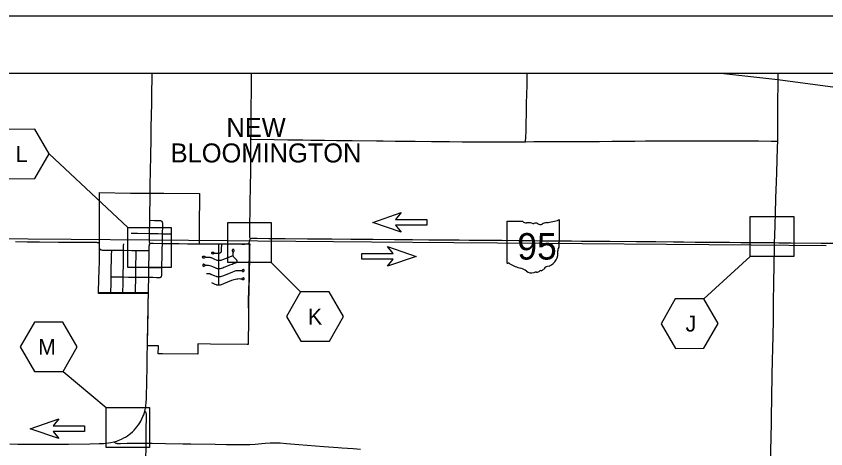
# Model space of a CAD drawing. Extents: x 0 to 680, y 0 to 440.
# Drawn here: x 190.2 to 332.1, y 364.2 to 440 of the extents above; entities that cross this region are included whole.
import ezdxf

# ---------------------------------------------------------------- set-up
doc = ezdxf.new("R2010")
doc.units = 0
for name, color, linetype in [('DV_X_Corp_Line', 7, 'Continuous'), ('GM_X_City_Street', 7, 'Continuous'), ('GM_X_Corporation_Text', 7, 'Continuous'), ('GM_X_County_Road', 7, 'Continuous'), ('GM_X_State_Location', 7, 'Continuous'), ('GM_X_State_Route', 7, 'Continuous'), ('GM_X_State_Shield', 7, 'Continuous'), ('GM_X_Township_Road', 7, 'Continuous'), ('PM_P_Cells', 7, 'Continuous'), ('RD_X_RR_2', 7, 'Continuous'), ('SC_Shading3', 7, 'Continuous'), ('SH_Border', 7, 'Continuous'), ('SH_Cut_Line', 7, 'Continuous'), ('SH_Text', 7, 'Continuous')]:
    doc.layers.add(name, color=color, linetype=linetype)

msp = doc.modelspace()

# ---------------------------------------------------------------- linework, layer by layer
at = {"layer": 'DV_X_Corp_Line'}
msp.add_lwpolyline([(231.1, 399.91), (231.09, 399.7), (231.09, 399.37), (231.08, 398.58), (231.07, 398.08), (231.07, 397.98), (231.01, 394.64), (230.96, 392.12), (230.92, 389.86), (230.87, 387.26), (230.87, 386.43), (230.84, 383.1), (230.84, 382.49), (230.64, 382.49), (224.26, 382.54), (222.03, 382.57), (222.02, 380.76), (215.82, 380.81), (215.09, 380.82), (215.11, 382.12), (215.11, 382.22), (214.91, 382.22), (213.52, 382.23), (213.39, 382.23), (213.19, 382.23), (213.2, 382.65), (213.22, 383.91), (213.24, 384.93), (213.24, 385.28), (213.26, 386.01), (213.31, 389.08), (213.31, 389.18), (213.31, 389.21), (213.33, 390.09), (213.35, 390.87), (213.36, 391.38), (213.16, 391.38), (211.27, 391.39), (210.02, 391.4), (205.38, 391.42), (204.59, 391.43), (204.59, 391.48), (204.59, 391.63), (204.59, 391.68), (204.6, 391.83), (204.61, 392.21), (204.62, 392.6), (204.64, 392.98), (204.65, 393.37), (204.67, 393.75), (204.68, 394.03), (204.68, 394.14), (204.69, 394.52), (204.71, 394.91), (204.72, 395.29), (204.73, 395.68), (204.75, 396.06), (204.76, 396.45), (204.77, 398.01), (204.77, 398.8), (204.78, 400.39), (204.78, 400.51), (204.78, 400.59), (204.78, 400.84), (204.78, 401.17), (204.78, 403.01), (204.76, 409.08), (210.21, 409), (211.53, 408.99), (213.48, 408.98), (213.68, 408.98), (213.88, 408.98), (214.76, 408.98), (214.87, 408.97), (216.04, 408.97), (222.33, 408.93), (222.26, 402.94), (222.24, 401.1), (222.24, 400.98), (222.25, 400.32), (222.25, 400.18), (222.25, 400.12), (223.84, 400.11), (225.4, 400.12), (225.64, 400.12), (227.83, 400.13), (228.56, 400.1), (229.18, 400.09), (229.77, 400.09), (231.1, 400.09)], close=True, dxfattribs=at)
at = {"layer": 'GM_X_City_Street'}
msp.add_line((225.68, 394.35), (225.69, 395.76), dxfattribs=at)
for points in [[(213.52, 400.79), (213.52, 401.42), (213.53, 401.93), (213.59, 404.23)], [(213.59, 404.23), (214.39, 404.22), (215.04, 404.22), (215.14, 404.21), (215.25, 404.21), (215.36, 404.19), (215.46, 404.17), (215.57, 404.13), (215.62, 404.1), (215.69, 404.06)], [(215.82, 400.74), (215.82, 401.47), (215.82, 401.89), (215.83, 402.23), (215.85, 402.89), (215.85, 403.32), (215.86, 403.64), (215.85, 403.76), (215.84, 403.8), (215.82, 403.87), (215.8, 403.91), (215.78, 403.96), (215.74, 404.01), (215.69, 404.06)], [(210.31, 401.98), (211.44, 401.95), (213.43, 401.93), (213.53, 401.93)], [(213.53, 401.93), (215.05, 401.91), (215.82, 401.89), (217, 401.89), (217.43, 401.88)], [(213.64, 400.16), (213.61, 400.22), (213.58, 400.27), (213.55, 400.33), (213.54, 400.39), (213.53, 400.43), (213.52, 400.49), (213.52, 400.54), (213.52, 400.6), (213.52, 400.79)], [(215.56, 394.29), (215.6, 394.33), (215.63, 394.37), (215.65, 394.4), (215.67, 394.44), (215.69, 394.54), (215.71, 394.65), (215.71, 394.76), (215.71, 395.3), (215.7, 395.96), (215.72, 396.6), (215.75, 397.57), (215.77, 398.33), (215.78, 398.99), (215.79, 399.21), (215.79, 399.51), (215.8, 399.83), (215.81, 399.97), (215.81, 400.18), (215.82, 400.43), (215.82, 400.74)], [(204.77, 399.29), (204.8, 399.23), (204.82, 399.19), (204.84, 399.16), (204.87, 399.14), (204.89, 399.13), (204.92, 399.11), (204.96, 399.09), (205.01, 399.06), (205.06, 399.05), (205.11, 399.04), (205.33, 399.01), (205.76, 399), (206.94, 399), (207.29, 399), (208.16, 398.99), (208.7, 398.99), (208.99, 398.99), (210.44, 398.96), (211.2, 398.95), (212.62, 398.92), (213.28, 398.92), (213.49, 398.92)], [(206.78, 391.59), (206.78, 391.74), (206.8, 392.97), (206.8, 393.63), (206.8, 394.31), (206.8, 395.05), (206.84, 396.15), (206.86, 396.92), (206.91, 398.34), (206.93, 398.78), (206.94, 399)], [(208.88, 391.58), (208.88, 391.72), (208.92, 393.11), (208.93, 394.31), (208.95, 395.2), (208.96, 396.07), (208.97, 397.5), (208.99, 398.99), (209.01, 399.8), (209.02, 400.13)], [(211.11, 391.56), (211.11, 391.7), (211.1, 392.02), (211.13, 394.1), (211.13, 394.28), (211.15, 395.19), (211.17, 396.06), (211.17, 396.82), (211.19, 397.58), (211.21, 398.24), (211.21, 398.67), (211.2, 398.95)], [(225.72, 398.41), (225.69, 398.63), (225.68, 398.89), (225.69, 399.86), (225.69, 400.11)], [(225.72, 398.41), (225.9, 398.51), (225.99, 398.57), (226.04, 398.6), (226.08, 398.63), (226.12, 398.68), (226.14, 398.73), (226.15, 398.78), (226.16, 398.83), (226.17, 398.94), (226.18, 399.28), (226.19, 399.92), (226.19, 400.1)], [(228.15, 397.98), (228.18, 398.04), (228.2, 398.11), (228.21, 398.2), (228.21, 398.29), (228.22, 398.49), (228.22, 398.6), (228.24, 398.65), (228.26, 398.7), (228.32, 398.79), (228.36, 398.89), (228.37, 398.94), (228.37, 399), (228.35, 399.06), (228.33, 399.09), (228.31, 399.11), (228.25, 399.13), (228.2, 399.14), (228.15, 399.13), (228.1, 399.09), (228.06, 399.04), (228.05, 399.01), (228.04, 398.97), (228.04, 398.93), (228.05, 398.88), (228.1, 398.77), (228.14, 398.73), (228.2, 398.69)], [(223.37, 397.77), (223.24, 397.66), (223.14, 397.62), (223.03, 397.6), (222.95, 397.62), (222.9, 397.65), (222.87, 397.71), (222.85, 397.78), (222.85, 397.84), (222.87, 397.91), (222.91, 397.95), (222.96, 397.96), (223.01, 397.97), (223.09, 397.96), (223.19, 397.92), (223.23, 397.9), (223.28, 397.86), (223.38, 397.82), (223.49, 397.8), (223.82, 397.8), (224.03, 397.78), (224.14, 397.76), (224.24, 397.73), (224.34, 397.69), (224.94, 397.42), (225.24, 397.3), (225.35, 397.27), (225.45, 397.25), (225.67, 397.23), (225.7, 397.23)], [(224.88, 398.45), (224.78, 398.36), (224.72, 398.33), (224.67, 398.31), (224.63, 398.31), (224.56, 398.33), (224.51, 398.35), (224.47, 398.4), (224.46, 398.44), (224.46, 398.49), (224.46, 398.55), (224.49, 398.6), (224.54, 398.63), (224.6, 398.64), (224.65, 398.65), (224.72, 398.65), (224.76, 398.62), (224.79, 398.59), (224.84, 398.55), (224.88, 398.52), (224.93, 398.5), (224.98, 398.48), (225.09, 398.47), (225.31, 398.47), (225.52, 398.45), (225.72, 398.41)], [(225.69, 395.76), (225.75, 395.76), (225.85, 395.77), (225.96, 395.79), (226.17, 395.85), (226.38, 395.93), (226.58, 396), (226.79, 396.09), (227.09, 396.2), (227.6, 396.41), (228.01, 396.57), (228.21, 396.66), (228.31, 396.69), (228.62, 396.8), (228.72, 396.84), (228.78, 396.86), (228.83, 396.9), (228.87, 396.93), (228.9, 396.98), (228.9, 397.04), (228.9, 397.09), (228.89, 397.16), (228.87, 397.21), (228.84, 397.25), (228.81, 397.29), (228.74, 397.37), (228.35, 397.76), (228.24, 397.88), (228.15, 397.98)], [(225.7, 397.23), (225.71, 397.67), (225.72, 398.41)], [(225.7, 397.23), (225.78, 397.22), (225.89, 397.23), (225.99, 397.25), (226.1, 397.27), (226.2, 397.31), (227.01, 397.62), (227.72, 397.89), (227.93, 397.96), (228.01, 397.98), (228.07, 397.99), (228.15, 397.98)], [(213.43, 395.94), (213.56, 395.94), (214.16, 395.94), (215.16, 395.94), (215.59, 395.95), (215.7, 395.96)], [(223.28, 396.39), (223.15, 396.49), (223.1, 396.51), (223.04, 396.52), (223, 396.52), (222.94, 396.49), (222.9, 396.46), (222.87, 396.41), (222.86, 396.35), (222.88, 396.29), (222.91, 396.25), (222.95, 396.22), (223, 396.21), (223.06, 396.2), (223.11, 396.22), (223.16, 396.24), (223.23, 396.3), (223.29, 396.34), (223.34, 396.36), (223.4, 396.37), (223.5, 396.38), (223.66, 396.38), (223.88, 396.35), (224.1, 396.31), (224.3, 396.25), (224.61, 396.12), (225.01, 395.94), (225.21, 395.85), (225.31, 395.82), (225.42, 395.79), (225.53, 395.77), (225.64, 395.77), (225.69, 395.76)], [(225.69, 395.76), (225.69, 395.8), (225.69, 396.68), (225.7, 397.23)], [(223.55, 394.9), (223.88, 394.92), (223.99, 394.91), (224.09, 394.89), (224.3, 394.82), (225, 394.5), (225.21, 394.42), (225.31, 394.39), (225.42, 394.36), (225.53, 394.34), (225.64, 394.34), (225.68, 394.35)], [(225.68, 394.35), (225.86, 394.36), (226.05, 394.39), (226.18, 394.43), (226.39, 394.51), (228.03, 395.16), (228.54, 395.35), (228.75, 395.42), (228.86, 395.44), (228.97, 395.45), (229.19, 395.45), (229.41, 395.44), (229.52, 395.43), (229.63, 395.41), (229.73, 395.36), (229.82, 395.31), (229.86, 395.28), (229.92, 395.27), (229.98, 395.27), (230.04, 395.27), (230.09, 395.3), (230.13, 395.35), (230.15, 395.4), (230.15, 395.45), (230.14, 395.51), (230.11, 395.55), (230.06, 395.58), (230.01, 395.59), (229.96, 395.59), (229.91, 395.57), (229.85, 395.55), (229.7, 395.43)], [(206.8, 394.31), (206.93, 394.31), (207.81, 394.31), (208.93, 394.31), (209.89, 394.29), (211.13, 394.28), (211.63, 394.27), (212.62, 394.26), (213.41, 394.25)], [(213.41, 394.25), (213.67, 394.25), (214.12, 394.24), (214.79, 394.2), (215.12, 394.2), (215.23, 394.2), (215.28, 394.2), (215.34, 394.21), (215.4, 394.23), (215.45, 394.24), (215.5, 394.26), (215.53, 394.27), (215.56, 394.29)], [(224.39, 393.32), (225, 393.06), (225.21, 392.98), (225.31, 392.95), (225.42, 392.93), (225.53, 392.91), (225.64, 392.9), (225.67, 392.9)], [(225.67, 392.9), (225.67, 392.97), (225.67, 393.59), (225.68, 394.35)], [(225.67, 392.9), (225.74, 392.9), (225.85, 392.91), (225.96, 392.93), (226.17, 392.99), (226.58, 393.14), (227.99, 393.72), (228.4, 393.87), (228.61, 393.93), (228.83, 393.97), (229.04, 394), (229.26, 394.01), (229.48, 394), (229.59, 393.99), (229.64, 393.97), (229.69, 393.96), (229.74, 393.93), (229.78, 393.9), (229.84, 393.87), (229.89, 393.86), (229.94, 393.84), (229.99, 393.83), (230.05, 393.84), (230.1, 393.86), (230.13, 393.9), (230.15, 393.96), (230.15, 394.01), (230.14, 394.05), (230.12, 394.08), (230.08, 394.12), (230.04, 394.14), (229.99, 394.14), (229.93, 394.13), (229.88, 394.12), (229.7, 394.01)], [(204.6, 391.61), (205.82, 391.6), (206.78, 391.59), (207.79, 391.58), (208.88, 391.58), (209.96, 391.57), (211.11, 391.56), (212.14, 391.56), (213.34, 391.56)]]:
    msp.add_lwpolyline(points, dxfattribs=at)
at = {"layer": 'GM_X_County_Road'}
for points in [[(213.67, 408.96), (213.67, 409.69), (213.74, 413.52), (213.76, 414.83), (213.78, 416.03), (213.82, 418), (213.86, 420.51), (213.94, 424.78), (213.97, 426.75), (214.02, 429.04), (214.03, 430)], [(231.33, 418.44), (231.34, 419.77), (231.36, 421.63), (231.38, 424.59), (231.4, 426.34), (231.4, 427.76), (231.42, 429.84), (231.42, 430)], [(231.26, 401), (231.19, 401.1), (231.13, 401.24), (231.11, 401.36), (231.1, 401.42), (231.1, 401.48), (231.1, 402.05), (231.12, 403.8), (231.16, 405.66), (231.19, 406.76), (231.19, 407.85), (231.22, 409.49), (231.28, 413.43), (231.31, 416.71), (231.33, 418.44)], [(213.59, 404.23), (213.59, 404.6), (213.62, 405.92), (213.64, 407.44), (213.66, 408.53), (213.67, 408.96)], [(190.03, 400.49), (192.11, 400.48), (194.29, 400.45), (197.57, 400.43), (199.76, 400.41), (201.62, 400.4), (204.13, 400.38), (204.25, 400.38), (204.35, 400.37), (204.42, 400.37), (204.46, 400.36), (204.5, 400.35), (204.53, 400.34), (204.56, 400.32), (204.58, 400.3)], [(204.58, 400.3), (204.61, 400.28), (204.66, 400.24), (204.69, 400.19), (204.72, 400.15), (204.74, 400.1), (204.75, 400.07), (204.75, 400.03), (204.75, 399.95), (204.75, 399.72), (204.75, 399.49), (204.75, 399.44), (204.75, 399.38), (204.76, 399.35), (204.77, 399.33), (204.77, 399.29)], [(212.94, 365.18), (212.95, 365.83), (212.97, 368.12), (212.99, 369.22), (213, 369.98), (213, 370.2), (212.99, 370.3), (212.97, 370.41), (212.94, 370.51), (212.89, 370.6), (212.74, 370.86)], [(207.29, 365.39), (207.36, 365.34), (207.45, 365.29), (207.54, 365.24), (207.66, 365.2), (207.8, 365.15), (207.9, 365.13), (208.12, 365.12), (208.44, 365.12), (209.65, 365.17), (211.51, 365.2), (212.27, 365.2), (212.94, 365.18)], [(212.24, 347.98), (212.27, 348.35), (212.37, 349.99), (212.53, 352.39), (212.69, 354.68), (212.83, 357.08), (212.86, 358.06), (212.91, 362.44), (212.93, 364.41), (212.94, 365.18)], [(212.94, 365.18), (214.02, 365.15), (216.32, 365.12), (219.38, 365.08), (220.81, 365.05), (225.07, 364.99), (227.04, 364.96), (229.34, 364.93), (230.43, 364.94), (230.48, 364.94), (230.54, 364.94)], [(230.54, 364.94), (231.12, 364.96), (232.08, 365.02), (233.83, 365.15), (234.7, 365.21), (235.36, 365.24), (235.91, 365.23), (236.45, 365.21), (237.55, 365.12), (239.73, 364.95), (244.09, 364.6), (246.6, 364.4), (247.26, 364.36)], [(247.26, 364.36), (249.22, 364.22), (250.53, 364.15)]]:
    msp.add_lwpolyline(points, dxfattribs=at)
at = {"layer": 'GM_X_State_Route'}
for p, q in [((195.93, 415.86), (209.72, 402.96)), ((310.68, 390.47), (318.81, 397.87)), ((240.03, 391.69), (234.88, 396.82)), ((198.39, 377.74), (205.93, 371.44))]:
    msp.add_line(p, q, dxfattribs=at)
for points in [[(193.42, 420.19), (188.42, 420.17), (185.93, 415.83), (188.44, 411.51), (193.44, 411.53), (195.93, 415.86)], [(245.03, 391.71), (240.03, 391.69), (237.54, 387.35), (240.06, 383.03), (245.06, 383.05), (247.54, 387.38)], [(310.68, 390.47), (305.68, 390.45), (303.19, 386.11), (305.7, 381.79), (310.7, 381.81), (313.19, 386.14)], [(198.37, 386.4), (193.37, 386.39), (190.88, 382.05), (193.39, 377.73), (198.39, 377.74), (200.88, 382.08)]]:
    msp.add_lwpolyline(points, close=True, dxfattribs=at)
for points in [[(213.34, 391.35), (213.34, 391.56), (213.37, 392.58), (213.4, 393.78), (213.41, 394.25), (213.42, 394.45), (213.43, 395.74), (213.43, 395.94), (213.48, 398.37), (213.49, 398.92), (213.49, 399.19), (213.5, 399.46), (213.51, 399.71), (213.53, 399.87), (213.53, 399.97), (213.55, 400.02), (213.56, 400.06), (213.6, 400.12), (213.64, 400.16), (213.74, 400.19), (213.81, 400.2), (213.97, 400.21), (214.19, 400.21), (215.81, 400.18), (217.67, 400.15), (218.77, 400.14), (220.18, 400.13), (222.26, 400.12)], [(222.26, 400.12), (223.7, 400.11), (225.56, 400.11), (225.69, 400.11), (226.19, 400.1), (229.71, 400.07), (230.25, 400.07), (230.58, 400.09), (230.66, 400.1), (230.75, 400.12), (230.79, 400.13), (230.83, 400.15), (230.86, 400.16), (230.9, 400.18), (230.92, 400.19), (230.95, 400.22)], [(230.95, 400.22), (230.98, 400.25), (231, 400.29), (231.02, 400.34), (231.04, 400.38), (231.07, 400.55), (231.11, 400.73), (231.13, 400.83), (231.19, 400.92), (231.26, 401)], [(231.26, 401), (231.35, 401.05), (231.45, 401.08), (231.59, 401.09), (231.73, 401.09), (232.4, 401.08), (234.48, 401.06), (237.32, 401.04), (241.26, 401), (242.9, 400.99), (245.52, 400.97), (248.8, 400.94), (251.1, 400.93), (252.74, 400.92), (256.46, 400.89), (258.43, 400.87), (259.63, 400.86), (262.48, 400.82), (264.88, 400.81), (267.84, 400.79), (269.59, 400.77), (272.21, 400.75), (273.74, 400.75), (275.27, 400.73), (278.23, 400.71), (280.41, 400.68), (282.49, 400.66), (287.52, 400.62), (289.27, 400.6), (291.13, 400.59), (294.2, 400.56), (298.9, 400.53), (302.29, 400.5), (305.35, 400.46), (307.1, 400.46), (309.18, 400.42), (311.04, 400.42), (312.13, 400.41), (315.2, 400.38), (317.16, 400.37), (318.69, 400.34), (320.23, 400.34), (321.98, 400.33), (323.09, 400.32), (323.84, 400.31), (326.02, 400.29), (331.27, 400.25), (335.32, 400.21)], [(213.18, 382.21), (213.19, 382.74), (213.25, 385.27), (213.26, 386.28), (213.28, 387.57), (213.3, 388.76), (213.32, 389.8), (213.34, 391.35)], [(189.07, 365.05), (190.49, 365.02), (191.58, 365.01), (193.44, 365), (194.43, 364.99), (197.28, 365), (199.35, 365.02), (203.08, 365.07), (204.72, 365.1), (205.48, 365.12), (205.92, 365.16), (206.36, 365.21), (206.79, 365.28), (207.29, 365.39), (207.55, 365.47), (207.8, 365.55), (208.03, 365.63), (208.34, 365.75), (208.64, 365.89), (209.03, 366.09), (209.31, 366.25), (209.68, 366.49), (209.95, 366.68), (210.21, 366.89), (210.54, 367.17), (210.85, 367.48), (211.15, 367.8), (211.35, 368.06), (211.62, 368.41), (211.86, 368.77), (212.02, 369.06), (212.22, 369.45), (212.4, 369.85), (212.52, 370.15), (212.66, 370.57), (212.74, 370.86), (212.84, 371.31), (212.91, 371.75), (212.98, 372.29), (213.02, 372.94), (213.04, 373.71), (213.08, 375.45), (213.12, 378.94), (213.16, 380.58), (213.18, 382.21)]]:
    msp.add_lwpolyline(points, dxfattribs=at)
at = {"layer": 'GM_X_State_Shield'}
for p, q in [((276.14, 403.89), (276.14, 396.85)), ((278.95, 404.01), (276.23, 404.01)), ((285.42, 400.5), (285.42, 404.19)), ((285.42, 400.5), (285.42, 400.5))]:
    msp.add_line(p, q, dxfattribs=at)
for centre, radius, start, end in [((276.24, 403.91), 0.108, 98.1301, 188.1301), ((279.59, 404.83), 1.04, 231.6195, 271.1119), ((279.94, 400.06), 3.74, 80.4867, 94.9883), ((280.79, 403.94), 0.301, 219.7921, 297.1024), ((281.23, 403.13), 0.626, 54.4667, 119.1411), ((282.04, 404.25), 0.753, 233.8562, 294.8282), ((283.37, 401.86), 1.98, 97.3462, 120.7689), ((282.11, 413.62), 9.84, 275.8445, 288.9065), ((285.32, 404.2), 0.103, 351.8621, 97.738), ((285.4, 400.23), 0.16, 107.944, 210.337), ((284.38, 399.77), 0.96, 340.033, 23.6496), ((285.31, 400.49), 0.111, 289.6038, 7.7341), ((282.66, 398.49), 2.46, 292.3089, 8.9858), ((285.79, 398.96), 0.698, 136.8065, 186.9296), ((276.25, 396.83), 0.108, 171.9584, 258.3066), ((276.26, 397.55), 0.828, 267.339, 280.6039), ((276.43, 396.44), 0.298, 29.7484, 93.2717), ((280.2, 402.77), 7.11, 240.4129, 257.1985), ((283.7, 394.87), 1.35, 94.4031, 142.5768), ((278.08, 393.68), 2.22, 47.1842, 75.836), ((280.49, 396.41), 1.41, 230.7004, 286.2918), ((281.3, 393.97), 1.16, 85.6951, 111.2099), ((281.4, 395.88), 0.752, 268.777, 315.5493), ((282.08, 395.2), 0.212, 65.7517, 132.6484), ((281.99, 396.17), 0.795, 282.8732, 323.2771)]:
    msp.add_arc(centre, radius, start, end, dxfattribs=at)
at = {"layer": 'GM_X_Township_Road'}
for points in [[(279.46, 418.01), (279.46, 418.13), (279.49, 418.68), (279.53, 419.99), (279.57, 421.41), (279.6, 422.72), (279.64, 424.68), (279.68, 426.32), (279.72, 427.85), (279.75, 429.81), (279.75, 430)], [(323.64, 418.1), (323.65, 418.43), (323.66, 420.51), (323.67, 423.14), (323.68, 425.76), (323.71, 427.4), (323.71, 428.38), (323.72, 429.04), (323.72, 429.29), (323.72, 429.91), (323.73, 430)], [(231.33, 418.44), (231.5, 418.44), (235.38, 418.4), (237.78, 418.36), (240.41, 418.32), (241.83, 418.3), (244.24, 418.26), (246.32, 418.24), (249.05, 418.21), (253.32, 418.16), (254.52, 418.14), (256.6, 418.12), (258.46, 418.1), (260.1, 418.08), (262.95, 418.06), (266.12, 418.02), (268.31, 417.99), (272.03, 417.98), (276.62, 418.01), (278.7, 418), (279.46, 418.01)], [(279.46, 418.01), (280.89, 418.02), (283.3, 418.03), (284.83, 418.03), (287.45, 418.03), (290.08, 418.04), (292.38, 418.05), (294.57, 418.08), (298.61, 418.12), (300.47, 418.13), (302.23, 418.14), (305.95, 418.16), (309.77, 418.17), (312.07, 418.16), (314.04, 418.15), (317.98, 418.13), (320.28, 418.13), (322.47, 418.12), (323.23, 418.12), (323.45, 418.11), (323.64, 418.1)], [(323.09, 400.32), (323.1, 400.64), (323.12, 401.27), (323.2, 403.68), (323.24, 405.32), (323.33, 408.16), (323.42, 410.89), (323.48, 412.64), (323.54, 414.72), (323.61, 417.01), (323.64, 418.1)], [(230.92, 390.38), (230.95, 391.89), (231, 393.76), (231.02, 394.74), (231.03, 396.61), (231.06, 397.71), (231.07, 398.8), (231.07, 399.35), (231.06, 399.68), (231.06, 399.76), (231.05, 399.84), (231.04, 399.92), (231.03, 399.98), (231.01, 400.06), (230.99, 400.12), (230.97, 400.17), (230.95, 400.22)], [(322.27, 352.88), (322.26, 353.71), (322.29, 355.13), (322.31, 356.44), (322.36, 358.52), (322.46, 363.66), (322.5, 366.39), (322.55, 368.58), (322.57, 370.87), (322.59, 372.08), (322.61, 373.28), (322.69, 377), (322.74, 379.84), (322.78, 381.59), (322.88, 386.62), (322.9, 388.04), (322.93, 390.67), (322.97, 392.53), (323.02, 397.12), (323.05, 398.65), (323.08, 400.07), (323.09, 400.32)], [(230.91, 388.82), (230.92, 390.13), (230.92, 390.38)]]:
    msp.add_lwpolyline(points, dxfattribs=at)
at = {"layer": 'PM_P_Cells'}
for p, q in [((252.66, 403.87), (257.66, 405.6)), ((257.66, 405.6), (256.66, 404.37)), ((252.66, 403.87), (252.66, 403.87)), ((257.66, 402.13), (252.66, 403.87)), ((256.66, 404.37), (262.16, 404.37)), ((262.16, 403.37), (256.66, 403.37)), ((256.66, 403.37), (257.66, 402.13)), ((262.16, 404.37), (262.16, 403.37)), ((262.16, 403.87), (262.16, 403.87)), ((256.27, 398.4), (255.27, 399.64)), ((255.27, 399.64), (260.27, 397.9)), ((250.77, 397.4), (250.77, 398.4)), ((250.77, 398.4), (256.27, 398.4)), ((250.77, 397.9), (250.77, 397.9)), ((256.27, 397.4), (250.77, 397.4)), ((260.27, 397.9), (255.27, 396.17)), ((255.27, 396.17), (256.27, 397.4)), ((260.27, 397.9), (260.27, 397.9)), ((192.64, 367.71), (197.64, 369.45)), ((197.64, 369.45), (196.64, 368.21)), ((192.64, 367.71), (192.64, 367.71)), ((197.64, 365.98), (192.64, 367.71)), ((196.64, 368.21), (202.14, 368.21)), ((202.14, 368.21), (202.14, 367.21)), ((202.14, 367.71), (202.14, 367.71)), ((202.14, 367.21), (196.64, 367.21)), ((196.64, 367.21), (197.64, 365.98))]:
    msp.add_line(p, q, dxfattribs=at)
at = {"layer": 'RD_X_RR_2'}
for points in [[(313.66, 430), (323.68, 428.91), (333.73, 427.55), (360.02, 424.5), (387.32, 421.44), (413.77, 418.16), (438.79, 415.43), (466.92, 412.47)], [(332.13, 399.75), (318.98, 399.86), (274.52, 400.24), (266.85, 400.3), (252.47, 400.42), (232.51, 400.6), (227.22, 400.64), (213.54, 400.75), (199.79, 400.86), (177.18, 401.05)]]:
    msp.add_lwpolyline(points, dxfattribs=at)
at = {"layer": 'SC_Shading3'}
msp.add_lwpolyline([(231.1, 399.91), (231.09, 399.7), (231.09, 399.37), (231.08, 398.58), (231.07, 398.08), (231.07, 397.98), (231.01, 394.64), (230.96, 392.12), (230.92, 389.86), (230.87, 387.26), (230.87, 386.43), (230.84, 383.1), (230.84, 382.49), (230.64, 382.49), (224.26, 382.54), (222.03, 382.57), (222.02, 380.76), (215.82, 380.81), (215.09, 380.82), (215.11, 382.12), (215.11, 382.22), (214.91, 382.22), (213.52, 382.23), (213.39, 382.23), (213.19, 382.23), (213.2, 382.65), (213.22, 383.91), (213.24, 384.93), (213.24, 385.28), (213.26, 386.01), (213.31, 389.08), (213.31, 389.18), (213.31, 389.21), (213.33, 390.09), (213.35, 390.87), (213.36, 391.38), (213.16, 391.38), (211.27, 391.39), (210.02, 391.4), (205.38, 391.42), (204.59, 391.43), (204.59, 391.48), (204.59, 391.63), (204.59, 391.68), (204.6, 391.83), (204.61, 392.21), (204.62, 392.6), (204.64, 392.98), (204.65, 393.37), (204.67, 393.75), (204.68, 394.03), (204.68, 394.14), (204.69, 394.52), (204.71, 394.91), (204.72, 395.29), (204.73, 395.68), (204.75, 396.06), (204.76, 396.45), (204.77, 398.01), (204.77, 398.8), (204.78, 400.39), (204.78, 400.51), (204.78, 400.59), (204.78, 400.84), (204.78, 401.17), (204.78, 403.01), (204.76, 409.08), (210.21, 409), (211.53, 408.99), (213.48, 408.98), (213.68, 408.98), (213.88, 408.98), (214.76, 408.98), (214.87, 408.97), (216.04, 408.97), (222.33, 408.93), (222.26, 402.94), (222.24, 401.1), (222.24, 400.98), (222.25, 400.32), (222.25, 400.18), (222.25, 400.12), (223.84, 400.11), (225.4, 400.12), (225.64, 400.12), (227.83, 400.13), (228.56, 400.1), (229.18, 400.09), (229.77, 400.09), (231.1, 400.09)], close=True, dxfattribs=at)
at = {"layer": 'SH_Border'}
for points in [[(30, 430), (670, 430), (670, 10), (30, 10)], [(318.81, 404.87), (326.44, 404.87), (326.44, 397.87), (318.81, 397.87)], [(227.25, 403.82), (234.88, 403.82), (234.88, 396.82), (227.25, 396.82)], [(209.72, 402.96), (217.35, 402.96), (217.35, 395.96), (209.72, 395.96)], [(205.93, 371.44), (213.55, 371.44), (213.55, 364.44), (205.93, 364.44)]]:
    msp.add_lwpolyline(points, close=True, dxfattribs=at)
at = {"layer": 'SH_Cut_Line'}
msp.add_lwpolyline([(0, 0), (680, 0), (680, 440), (0, 440)], close=True, dxfattribs=at)
at = {"layer": 'SH_Text'}
msp.add_lwpolyline([(30, 430), (466.92, 430), (466.92, 291.27), (342.9, 138.72), (30, 138.72)], close=True, dxfattribs=at)

# ---------------------------------------------------------------- texts
at = {"layer": 'GM_X_Corporation_Text'}
for s, height, p in [('NEW', 3.333, (227.02, 418.85)), ('BLOOMINGTON', 3.3333, (217.25, 414.37))]:
    msp.add_text(s, height=height, rotation=0, dxfattribs=at).set_placement(p)
at = {"layer": 'GM_X_State_Location'}
msp.add_text('95', height=0.00667, rotation=0, dxfattribs=at).set_placement((279, 399.42))
for s in ['s', 'r']:
    msp.add_text(s, height=0.00667, dxfattribs=at).set_placement((280.67, 399.9))
at = {"layer": 'GM_X_State_Route'}
for s, p in [('L', (190.1, 414.45)), ('K', (241.3, 385.97)), ('J', (307.49, 384.73)), ('M', (194.02, 380.66))]:
    msp.add_text(s, height=2.8, dxfattribs=at).set_placement(p)
at = {"layer": 'GM_X_State_Shield'}
msp.add_text('95', height=4.641, dxfattribs=at).set_placement((278.01, 397.35))

doc.saveas('drawing.dxf')
